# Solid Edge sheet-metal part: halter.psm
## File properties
Author: Administrator
Template: Normal.psm
Last saved by: ra-11
Revision: 8
Application: Solid Edge
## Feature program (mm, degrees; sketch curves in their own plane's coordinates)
base tab "unnamed BaseTab 1"
sheet metal cutout "unnamed SheetMetalCutout 1"
sheet metal cutout "unnamed SheetMetalCutout 2"
sheet metal cutout "unnamed SheetMetalCutout 3"
sheet metal cutout "unnamed SheetMetalCutout 4"
flange "unnamed Flange 1"
flange "unnamed Flange 2"
flange "unnamed Flange 3"
flange "unnamed Flange 4"
sketch for "unnamed Cutout 1" plane through (0, 20, 20.5) normal (0, -1, 0) x-axis (1, 0, 0)
  line (-6, 1.5) -> (-6, 16.5)
  line (6, 1.5) -> (6, 16.5)
extrude "unnamed Cutout 1" cut
sketch for "unnamed Cutout 2" plane through (0, -22, 20.5) normal (0, -1, 0) x-axis (1, 0, 0)
  line (-12, 4.5) -> (-21.921, 4.5)
  line (12, 4.5) -> (22.6566, 4.5)
extrude "unnamed Cutout 2" cut
sketch for "unnamed Cutout 3" plane through (0, -22, 20.5) normal (0, -1, 0) x-axis (1, 0, 0)
  circle centre (0, 1.5) radius 5
extrude "unnamed Cutout 3" cut
sketch for "unnamed Cutout 4" plane through (22, 0, -22.5) normal (1, 0, 0) x-axis (0, 1, 0)
  circle centre (0, -8.5) radius 7.5
extrude "unnamed Cutout 4" cut
sketch for "unnamed Cutout 5" plane through (22, 0, -22.5) normal (1, 0, 0) x-axis (0, 1, 0)
  line (-12, -8.5) -> (-24.6762, -8.5)
  line (12, -8.5) -> (22.1172, -8.5)
extrude "unnamed Cutout 5" cut
sketch for "unnamed Cutout 6" plane through (0, 0, 0) normal (0, 0, 1) x-axis (1, 0, 0)
  line (-6, -6) -> (6, -6)
  line (6, -6) -> (6, 6)
  line (6, 6) -> (-6, 6)
  line (-6, 6) -> (-6, -6)
extrude "unnamed Cutout 6" cut
